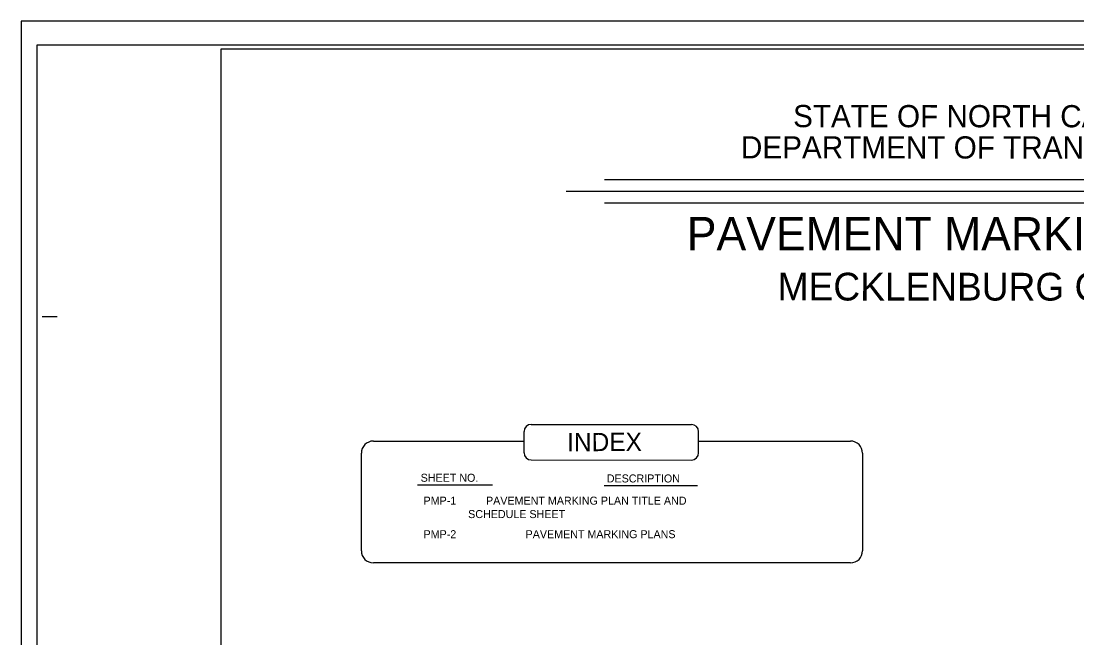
# Model space of a CAD drawing. Extents: x 2088685 to 2091711, y 751320 to 752417.
# Drawn here: x 2089192 to 2090071, y 751903 to 752417 of the extents above; entities that cross this region are included whole.
import ezdxf

# ---------------------------------------------------------------- set-up
doc = ezdxf.new("R2010")
doc.units = 0
for name, color, linetype in [('Default', 7, 'Continuous'), ('Sheet Block Title CELL', 7, 'Continuous'), ('Sheet Data Field CELL', 7, 'Continuous'), ('Sheet Plot Border Inside CELL', 7, 'Continuous'), ('Sheet Plot Border Outside CELL', 7, 'Continuous'), ('Sheet Title CELL', 7, 'Continuous')]:
    doc.layers.add(name, color=color, linetype=linetype)

msp = doc.modelspace()

# ---------------------------------------------------------------- linework, layer by layer
at = {"layer": 'Sheet Block Title CELL'}
msp.add_lwpolyline([(2090858, 752393.6), (2089358.33, 752393.49), (2089358.41, 751343.72), (2090858.08, 751343.83)], close=True, dxfattribs=at)
at = {"layer": 'Sheet Plot Border Inside CELL'}
msp.add_line((2089209.43, 752170.95), (2089221.93, 752170.96), dxfattribs=at)
msp.add_lwpolyline([(2090869.93, 752396.91), (2089204.86, 752396.79), (2089204.94, 751341.13), (2090870.01, 751341.25)], close=True, dxfattribs=at)
at = {"layer": 'Sheet Plot Border Outside CELL'}
msp.add_lwpolyline([(2090874.42, 752416.91), (2089191.88, 752416.79), (2089191.96, 751321.13), (2090874.5, 751321.25)], close=True, dxfattribs=at)
at = {"layer": 'Sheet Title CELL'}
for p, q in [((2089677.86, 752285.08), (2090369.97, 752285.08)), ((2089645.9, 752275.34), (2090400.31, 752275.34)), ((2089677.86, 752265.58), (2090369.97, 752265.58)), ((2089610.92, 752057.49), (2089610.93, 752075.13)), ((2089756.34, 752057.43), (2089756.35, 752075.06)), ((2089522.02, 752030.85), (2089584.58, 752030.82)), ((2089677.59, 752030.28), (2089755.31, 752030.25))]:
    msp.add_line(p, q, dxfattribs=at)
for points in [[(2089616.93, 752081.12), (2089750.35, 752081.06)], [(2089485.33, 752067.23), (2089610.92, 752067.23)], [(2089756.34, 752067.23), (2089882.89, 752067.23)], [(2089475.33, 751975.79), (2089475.33, 752057.23)], [(2089616.92, 752051.49), (2089750.34, 752051.43)], [(2089892.89, 752057.23), (2089892.89, 751975.79)], [(2089882.89, 751965.79), (2089485.33, 751965.79)]]:
    msp.add_lwpolyline(points, dxfattribs=at)
for centre, radius, start, end in [((2089616.93, 752075.12), 6, 89.97341, 179.97341), ((2089750.35, 752075.06), 6, 359.97341, 89.97341), ((2089485.33, 752057.23), 10, 90, 180), ((2089882.89, 752057.23), 10, 0, 90), ((2089616.92, 752057.49), 6, 179.97341, 269.97341), ((2089750.34, 752057.43), 6, 269.97341, 359.97341), ((2089485.33, 751975.79), 10, 180, 270), ((2089882.89, 751975.79), 10, 270, 0)]:
    msp.add_arc(centre, radius, start, end, dxfattribs=at)

# ---------------------------------------------------------------- texts
at = {"layer": 'Default'}
for s, height, rotation, p in [('INDEX', 15.257, 0.15565, (2089646.74, 752058.76)), ('SHEET NO.', 6.671, 359.97341, (2089524.74, 752033.36)), ('DESCRIPTION', 6.6709, 359.97341, (2089679.82, 752032.79))]:
    msp.add_text(s, height=height, rotation=rotation, dxfattribs=at).set_placement(p)
for s, height, p in [('PMP-1          PAVEMENT MARKING PLAN TITLE AND', 6.6709, (2089527.16, 752014.28)), ('               SCHEDULE SHEET', 6.6709, (2089527.16, 752003.11)), ('PMP-2 ', 6.671, (2089527.16, 751986.37)), ('  PAVEMENT MARKING PLANS', 6.6709, (2089607.21, 751986.37))]:
    msp.add_text(s, height=height, dxfattribs=at).set_placement(p)
at = {"layer": 'Sheet Data Field CELL'}
for s, height, p in [('STATE OF NORTH CAROLINA', 18.4936, (2089835.03, 752328.6)), ('DEPARTMENT OF TRANSPORTATION', 18.4936, (2089791.59, 752302.59)), ('PAVEMENT MARKING PLAN', 27.7403, (2089746.49, 752226.16)), ('MECKLENBURG COUNTY', 23.1165, (2089822.19, 752184.31))]:
    msp.add_text(s, height=height, rotation=359.97341, dxfattribs=at).set_placement(p)

doc.saveas('drawing.dxf')
